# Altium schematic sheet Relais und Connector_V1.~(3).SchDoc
size A4; SheetNumber: 6; SheetTotal: 7
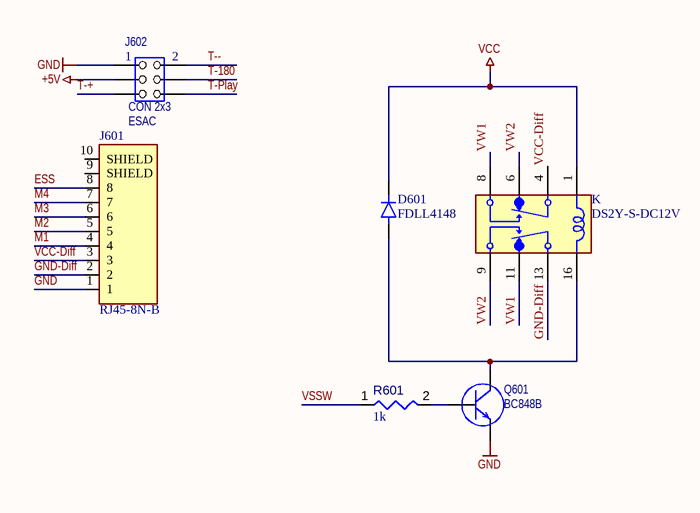
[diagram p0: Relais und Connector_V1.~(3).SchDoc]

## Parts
D601  FDLL4148  [DIOMELF3414N]
J601  RJ45-8N-B  [TE_RJ45-8N-B]
J602  CON 2x3  Use: ESAC  [J_2x3]
K  DS2Y-S-DC12V  [RELAY_DS2Y-S-DC12V]
Q601  BC848B  [SOT-23]
R601  value 1k  [RESC1608X55X25ML10T15]  (hidden comment: Resistor 1k +/-1% 0603 100 mW)

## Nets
+5V: J602.3
GND: J601.1 J602.1 Q601.2(E)
VCC: D601.C K.1(POS)
ESS: J601.8
GND-Diff: J601.2 K.13(COM2)
M1: J601.4
M2: J601.5
M3: J601.6
M4: J601.7
T-180: J602.4
T-+: J602.5
T--: J602.2
T-Play: J602.6
VCC-Diff: J601.3 K.4(COM1)
VSSW: R601.1
VW1: K.8(NO1) K.11(NC2)
VW2: K.6(NC1) K.9(NO2)
NetD601_A: D601.A K.16(NEG) Q601.3(C)
NetQ601_1: Q601.1(B) R601.2

Not connected (* = marked no-connect by the designer): J601 9(SHIELD) 10(SHIELD)

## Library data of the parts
D601 = FDLL4148: Diode Standard 100 V 200mA Surface Mount SOD-80; MF: ON Semiconductor
J601 = RJ45-8N-B: RJ Jack / Signal Line EMI/RFI Filters 6 TERM LOW PROFILE BLOCK INDUCTOR 8 PIN
J602 = J_THT_IDC 2x3: Stecker
K = DS2Y-S-DC12V: General Purpose Relay DPDT _2 Form C_ Through Hole; MF: Panasonic Electric
Q601 = Q_SMD_NPN: NPN Transistor
R601 = CMP-009-00014-5: Chip Resistor, 1 KOhm, +/-1%, 0.1 W, -55 to 155 degC, 0603 (1608 Metric); Voltage Rating: 50V; Power: 100mW; Tolerance: 1%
